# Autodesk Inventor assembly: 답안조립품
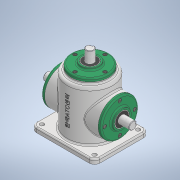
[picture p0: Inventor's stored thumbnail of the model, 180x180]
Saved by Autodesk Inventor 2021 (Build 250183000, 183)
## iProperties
Created: 2021-02
Part Number: 답안조립품
Document SubType Name: Assembly
Designer: 201-05
Author: 201-05
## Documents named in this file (16)
- C:\Users\201-05\Desktop\710214V1004\답안조립품.iam
- C:\Users\201-05\Desktop\710214V1004\본체.ipt
- C:\Users\201-05\Desktop\710214V1004\커버.ipt
- C:\Users\201-05\Desktop\710214V1004\베어링 6203.ipt
- C:\Users\201-05\Desktop\710214V1004\오일 실.ipt
- 오일 실.ipt
- C:\Users\201-05\Desktop\710214V1004\메인 축.ipt
- 메인 축.ipt
- C:\Users\201-05\Desktop\710214V1004\키 5x5.ipt
- C:\Users\201-05\Desktop\710214V1004\메인 베벨기어.ipt
- C:\Users\201-05\Desktop\710214V1004\서브 축.ipt
- 서브 축.ipt
- C:\Users\201-05\Desktop\710214V1004\키 4x4.ipt
- C:\Users\201-05\Desktop\710214V1004\서브 베벨기어.ipt
- C:\Users\201-05\Desktop\710214V1004\볼트 M4.ipt
- 볼트 M4.ipt
